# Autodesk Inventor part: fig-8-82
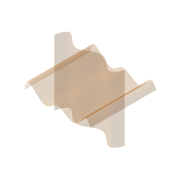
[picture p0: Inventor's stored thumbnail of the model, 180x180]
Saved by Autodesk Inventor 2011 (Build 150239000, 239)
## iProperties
Shininess: 64.0
Length Units: 11269
Angle Units: 11279
Time Units: 11290
Mass Units: 11283
Length Display Precision: 3
Angle Display Precision: 2
Compacted: True
Part Number: fig-8-82
Document SubType Name: Modeling
Created: 2003-08
Designer: Owner
Manufacturer: Standard
Standards Organization: Custom
Density: 1 g/cm^3
Density: 0.0
Volumn: 0.0
Area: 0.0
PropertySet Name: Model Information
Control State: 0
Master: False
Checked Out: False
Author: Owner
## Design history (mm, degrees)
sketch "Sketch1"
  geometry: 7 further points
  constraints: 7 other
  dimensions: "d0" = 80 horizontal distance of point (40, 1.742) point (-40, -4.065); "d1" = 40 horizontal distance of point (0, 0) point (-40, -4.065)
extrude_surface "ExtrusionSrf1" sketch "Sketch1" dims "d2" = 80, "d3" = 0
sketch "Sketch2"
  geometry: L1 (40, 0)-(40, -40) reference; L2 (-40, 0)-(-40, -40) reference; 7 further points
  constraints: 2 point on line, 7 other
extrude_surface "ExtrusionSrf2" sketch "Sketch2" dims "d4" = 80, "d5" = 0
sketch "Sketch3"
  geometry: 2 further points
  constraints: 4 other
sketch "Sketch4"
  geometry: L1 (52.956, 12.425)-(-10.974, 12.425); A1 r 27.841 centre (-10.974, -15.416) between (-10.974, 12.425) and (-7.259, -43.008)
  constraints: 2 end point, 2 point on circle, 1 centre point, 1 horizontal, 1 tangent
body "Srf1"
body "Srf2"
